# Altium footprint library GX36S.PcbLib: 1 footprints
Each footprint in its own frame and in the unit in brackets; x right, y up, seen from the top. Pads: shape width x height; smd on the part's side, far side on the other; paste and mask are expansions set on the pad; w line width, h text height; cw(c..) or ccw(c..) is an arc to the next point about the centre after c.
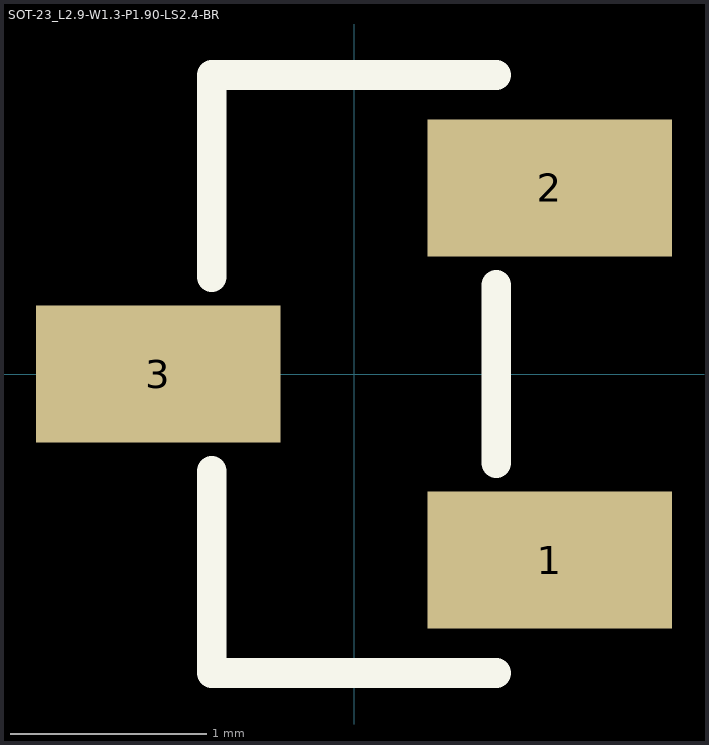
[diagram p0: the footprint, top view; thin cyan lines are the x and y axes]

## SOT-23_L2.9-W1.3-P1.90-LS2.4-BR [mm]
pads (3):
  rect 1.25x0.7 smd mask+0.051: 1(1,-0.95) 2(1,0.95) 3(-1,0)
Top Overlay:
  lines w0.152: -0.726,-0.495 -0.726,-1.526 0.726,-1.526 ; -0.726,0.495 -0.726,1.526 0.726,1.526 ; 0.726,-0.455 0.726,0.455
3D body "SOT23-3.STEP": height 1.05, standoff 0, extent -1.195,-1.506 1.205,1.494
